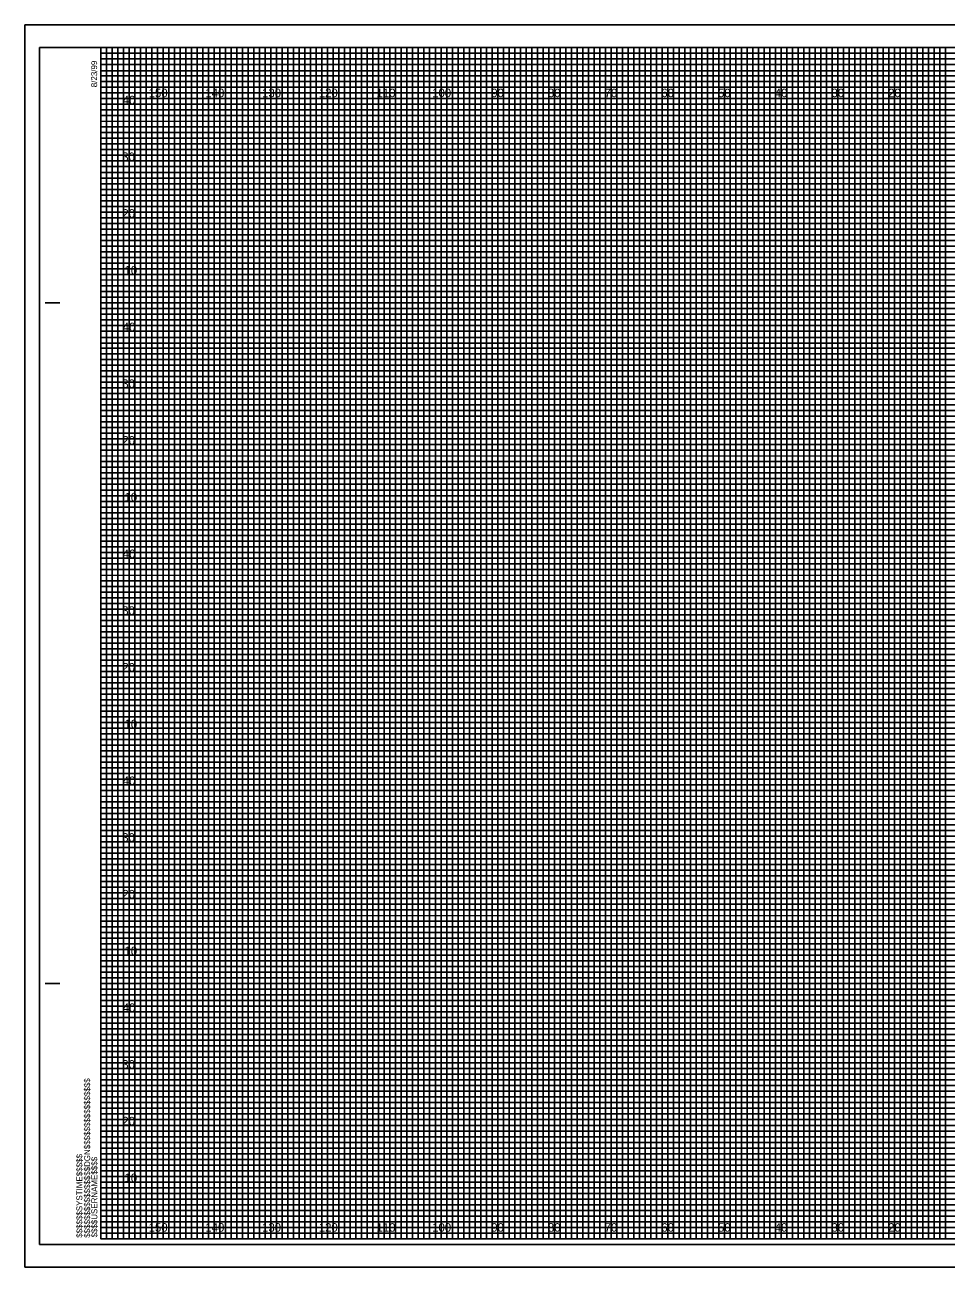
# Model space of a CAD drawing. Extents: x -13 to 323, y 215 to 434.
# Drawn here: x -13.4 to 149.1, y 215 to 434 of the extents above; entities that cross this region are included whole.
import ezdxf

# ---------------------------------------------------------------- set-up
doc = ezdxf.new("R2010")
doc.units = 0
for name, color, linetype in [('Exist Cross Section Cell', 7, 'Continuous'), ('Exist XS Center Line Elevation Label', 7, 'Continuous'), ('Exist XS Ground Line', 7, 'Continuous'), ('Prop XS Alignment Label', 7, 'Continuous'), ('Prop XS Ditch Standard Text', 7, 'Continuous'), ('Prop XS Earthwork Shape', 7, 'Continuous'), ('Prop XS Finish Grade', 7, 'Continuous'), ('Prop XS Finish Grade Earthwork', 7, 'Continuous'), ('Prop XS SE Text', 7, 'Continuous'), ('Prop XS Station Labels', 7, 'Continuous'), ('Prop XS Undercut Exc', 7, 'Continuous')]:
    doc.layers.add(name, color=color, linetype=linetype)

msp = doc.modelspace()

# ---------------------------------------------------------------- linework, layer by layer
at = {"layer": 'Exist XS Center Line Elevation Label'}
for points in [[(0, 430), (5, 430), (5, 220), (15, 220), (15, 430), (25, 430), (25, 220), (35, 220), (35, 430), (45, 430), (45, 220), (55, 220), (55, 430), (65, 430), (65, 220), (75, 220), (75, 430), (85, 430), (85, 220), (95, 220), (95, 430), (105, 430), (105, 220), (115, 220), (115, 430), (125, 430), (125, 220), (135, 220), (135, 430), (145, 430), (145, 220), (155, 220)], [(0, 425), (275, 425)], [(0, 405), (320, 405), (320, 415), (0, 415)], [(0, 385), (320, 385), (320, 395), (0, 395)], [(0, 365), (320, 365), (320, 375), (0, 375)], [(0, 345), (320, 345), (320, 355), (0, 355)], [(0, 325), (320, 325), (320, 335), (0, 335)], [(0, 305), (320, 305), (320, 315), (0, 315)], [(0, 285), (320, 285), (320, 295), (0, 295)], [(0, 265), (320, 265), (320, 275), (0, 275)], [(0, 245), (320, 245), (320, 255), (0, 255)], [(0, 225), (320, 225), (320, 235), (0, 235)]]:
    msp.add_lwpolyline(points, dxfattribs=at)
at = {"layer": 'Exist XS Ground Line'}
for p, q in [((10, 430), (0, 430)), ((10, 220), (10, 430)), ((30, 430), (20, 430)), ((20, 430), (20, 220)), ((30, 220), (30, 430)), ((50, 430), (40, 430)), ((40, 430), (40, 220)), ((50, 220), (50, 430)), ((70, 430), (60, 430)), ((60, 430), (60, 220)), ((70, 220), (70, 430)), ((90, 430), (80, 430)), ((80, 430), (80, 220)), ((90, 220), (90, 430)), ((110, 430), (100, 430)), ((100, 430), (100, 220)), ((110, 220), (110, 430)), ((130, 430), (120, 430)), ((120, 430), (120, 220)), ((130, 220), (130, 430)), ((150, 430), (140, 430)), ((140, 430), (140, 220)), ((20, 220), (10, 220)), ((40, 220), (30, 220)), ((60, 220), (50, 220)), ((80, 220), (70, 220)), ((100, 220), (90, 220)), ((120, 220), (110, 220)), ((140, 220), (130, 220))]:
    msp.add_line(p, q, dxfattribs=at)
for points in [[(0, 420), (320, 420), (320, 410), (0, 410)], [(0, 400), (320, 400), (320, 390), (0, 390)], [(0, 380), (320, 380), (320, 370), (0, 370)], [(0, 360), (320, 360), (320, 350), (0, 350)], [(0, 340), (320, 340), (320, 330), (0, 330)], [(0, 320), (320, 320), (320, 310), (0, 310)], [(0, 300), (320, 300), (320, 290), (0, 290)], [(0, 280), (320, 280), (320, 270), (0, 270)], [(0, 260), (320, 260), (320, 250), (0, 250)], [(0, 240), (320, 240), (320, 230), (0, 230)]]:
    msp.add_lwpolyline(points, dxfattribs=at)
at = {"layer": 'Prop XS Alignment Label'}
for p, q in [((0, 429), (260, 429)), ((260, 427.98), (0, 427.98)), ((0, 427.98), (0, 427)), ((0, 427), (260, 427)), ((260, 425.89), (0, 425.89)), ((0, 425.89), (0, 424)), ((0, 424), (320, 424))]:
    msp.add_line(p, q, dxfattribs=at)
for points in [[(0, 423), (270, 423), (320, 423), (320, 422), (0, 422)], [(0, 421), (320, 421), (320, 419), (0, 419)], [(0, 418), (320, 418), (320, 417), (0, 416.98)], [(0, 416), (320, 416), (320, 414), (0, 414)], [(0, 413), (320, 413), (320, 412), (0, 412)], [(0, 411), (320, 411), (320, 409), (0, 409)], [(0, 408), (320, 408), (320, 407), (0, 407)], [(0, 406), (320, 406), (320, 404), (0, 404)], [(0, 403), (320, 403), (320, 402), (0, 402)], [(0, 401), (320, 401), (320, 399), (0, 399)], [(0, 398), (320, 398), (320, 397), (0, 397)], [(0, 396), (320, 396), (320, 393.95), (320, 393), (320, 392), (0, 392)], [(0, 394), (320, 394), (320, 393), (0, 393)], [(0, 391), (320, 391), (320, 389), (0, 389.03)], [(0, 389.03), (320, 389), (320, 388), (0, 388)], [(0, 387), (320, 387), (320, 386), (0, 386)], [(0, 384), (320, 384), (320, 383), (0, 383)], [(0, 382), (320, 382), (320, 381), (0, 381)], [(-0.07, 378.89), (320, 378.89), (320, 377.88), (-0.07, 377.88)], [(0, 377), (320, 377), (320, 376), (0, 376)], [(0, 374), (320, 374), (320, 373), (0, 373)], [(0, 372), (320, 372), (320, 371), (0, 371)], [(0, 369), (320, 369), (320, 368), (0, 368)], [(0, 367), (320, 367), (320, 366), (0, 366)], [(0, 364), (320, 364), (320, 363), (0, 363)], [(0, 362), (320, 362), (320, 361), (0, 361)], [(0, 359), (320, 359), (319.99, 357.98), (0, 358)], [(0, 357), (320, 357), (320, 356), (0, 356)], [(0, 354), (320, 354), (320, 353), (0, 353)], [(0, 352), (320, 352), (320, 351), (0, 351)], [(0, 349), (320, 349), (320, 348), (0, 348)], [(0, 347), (320, 347), (320, 346), (0, 346)], [(0, 344), (320, 344), (320, 343), (0, 343)], [(0, 342), (320, 342), (320, 341), (0, 341)], [(0, 339), (320, 339), (320, 338), (0, 338)], [(0, 336.99), (320.07, 336.91), (320, 336), (0, 336)], [(0, 334), (320, 334), (320, 333), (0, 333)], [(0, 332), (320, 332), (320, 331), (0, 331)], [(0, 329), (320, 329), (320, 328), (0, 328)], [(0, 327), (320, 327), (320, 326), (0, 326)], [(0, 324), (320, 324), (320, 323), (0, 323)], [(0, 322), (320, 322), (320, 321), (0, 321)], [(0, 319), (320, 319), (320, 318), (0, 318)], [(0, 317), (320, 317), (320, 316), (0, 316)], [(0, 314), (320, 314), (320, 313), (0, 313)], [(0, 312), (320, 312), (320, 311), (0, 311)], [(0, 309), (320, 309), (320, 308), (0, 308)], [(0, 307), (320, 307), (320, 306), (0, 306)], [(0, 304), (320, 304), (320, 303), (0, 303)], [(0, 302), (320, 302), (320, 301), (0, 301)], [(0, 299), (320, 299), (319.99, 297.98), (0, 298)], [(0, 297), (320, 297), (320, 296), (0, 296)], [(0, 294), (320, 294), (320, 293), (0, 293)], [(0, 292), (320, 292), (320, 291), (0, 291)], [(0, 289), (320, 289), (320, 288), (0, 288)], [(0, 287), (320, 287), (320, 286), (0, 286)], [(0, 284), (320, 284), (320, 283), (0, 283)], [(0, 282), (320, 282), (320, 281), (0, 281)], [(0, 279), (320, 279), (320, 278), (0, 278)], [(0, 276.99), (320.07, 276.91), (320, 276), (0, 276)], [(0, 274), (320, 274), (320, 273), (0, 273)], [(0, 272), (320, 272), (320, 271), (0, 271)], [(0, 269), (320, 269), (320, 268), (0, 268)], [(0, 267), (320, 267), (320, 266), (0, 266)], [(0, 264), (320, 264), (320, 263), (0, 263)], [(0, 262), (320, 262), (320, 261), (0, 261)], [(0, 259), (320, 259), (320, 258), (0, 258)], [(0, 257), (320, 257), (320, 256), (0, 256)], [(0, 254), (320, 254), (320, 253), (0, 253)], [(0, 252), (320, 252), (320, 251), (0, 251)], [(0, 249), (320, 249), (320, 248), (0, 248)], [(0, 247), (320, 247), (320, 246), (0, 246)], [(0, 244), (320, 244), (320, 243), (0, 243)], [(0, 242), (320, 242), (320, 241), (0, 241)], [(0, 239), (320, 239), (320, 238), (0, 238)], [(0, 237), (320, 237), (320, 236), (0, 236)], [(0, 234), (320, 234), (320, 233), (0, 233)], [(0, 232), (320, 232), (320, 231), (0, 231)], [(0, 229), (320, 229), (320, 228), (0, 228)], [(0, 227), (320, 227), (320, 226), (0, 226)], [(0, 224), (320, 224), (320, 223), (0, 223)], [(0, 222), (320, 222), (320, 221), (0, 221)]]:
    msp.add_lwpolyline(points, dxfattribs=at)
at = {"layer": 'Prop XS Ditch Standard Text'}
for p, q in [((10, 220), (10, 430)), ((20, 220), (20, 430)), ((30, 220), (30, 430)), ((40, 220), (40, 430)), ((50, 220), (50, 430)), ((60, 220), (60, 430)), ((70, 220), (70, 430)), ((80, 220), (80, 430)), ((90, 220), (90, 430)), ((100, 220), (100, 430)), ((110, 220), (110, 430)), ((120, 220), (120, 430)), ((130, 220), (130, 430)), ((140, 220), (140, 430)), ((0, 420), (320, 420)), ((0, 410), (320, 410)), ((0, 400), (320, 400)), ((0, 390), (320, 390)), ((0, 380), (320, 380)), ((0, 370), (320, 370)), ((0, 360), (320, 360)), ((0, 350), (320, 350)), ((0, 340), (320, 340)), ((0, 330), (320, 330)), ((0, 320), (320, 320)), ((0, 310), (320, 310)), ((0, 300), (320, 300)), ((0, 290), (320, 290)), ((0, 280), (320, 280)), ((0, 270), (320, 270)), ((0, 260), (320, 260)), ((0, 250), (320, 250)), ((0, 240), (320, 240)), ((0, 230), (320, 230))]:
    msp.add_line(p, q, dxfattribs=at)
at = {"layer": 'Prop XS Earthwork Shape'}
for points in [[(0, 220), (1, 220), (1, 430), (2, 430), (2, 220)], [(2, 220), (3, 220), (3, 430), (4, 430), (4, 220)], [(5, 220), (6, 220), (6, 430), (7, 430), (7, 220)], [(7, 220), (8, 220), (8, 430), (9, 430), (9, 220)], [(10, 220), (11, 220), (11, 430), (12, 430), (12, 220)], [(12, 220), (13, 220), (13, 430), (14, 430), (14, 220)], [(15, 220), (16, 220), (16, 430), (17, 430), (17, 220)], [(17, 220), (18, 220), (18, 430), (19, 430), (19, 220)], [(20, 220), (21, 220), (21, 430), (22, 430), (22, 220)], [(22, 220), (23, 220), (23, 430), (24, 430), (24, 220)], [(25, 220), (26, 220), (26, 430), (27, 430), (27, 220)], [(27, 220), (28, 220), (28, 430), (29, 430), (29, 220)], [(30, 220), (31, 220), (31, 430), (32, 430), (32, 220)], [(32, 220), (33, 220), (33, 430), (34, 430), (34, 220)], [(35, 220), (36, 220), (36, 430), (37, 430), (37, 220)], [(37, 220), (38, 220), (38, 430), (39, 430), (39, 220)], [(40, 220), (41, 220), (41, 430), (42, 430), (42, 220)], [(42, 220), (43, 220), (43, 430), (44, 430), (44, 220)], [(45, 220), (46, 220), (46, 430), (47, 430), (47, 220)], [(47, 220), (48, 220), (48, 430), (49, 430), (49, 220)], [(50, 220), (51, 220), (51, 430), (52, 430), (52, 220)], [(52, 220), (53, 220), (53, 430), (54, 430), (54, 220)], [(55, 220), (56, 220), (56, 430), (57, 430), (57, 220)], [(57, 220), (58, 220), (58, 430), (59, 430), (59, 220)], [(60, 220), (61, 220), (61, 430), (62, 430), (62, 220)], [(62, 220), (63, 220), (63, 430), (64, 430), (64, 220)], [(65, 220), (66, 220), (66, 430), (67, 430), (67, 220)], [(67, 220), (68, 220), (68, 430), (69, 430), (69, 220)], [(70, 220), (71, 220), (71, 430), (72, 430), (72, 220)], [(72, 220), (73, 220), (73, 430), (74, 430), (74, 220)], [(75, 220), (76, 220), (76, 430), (77, 430), (77, 220)], [(77, 220), (78, 220), (78, 430), (79, 430), (79, 220)], [(80, 220), (81, 220), (81, 430), (82, 430), (82, 220)], [(82, 220), (83, 220), (83, 430), (84, 430), (84, 220)], [(85, 220), (86, 220), (86, 430), (87, 430), (87, 220)], [(87, 220), (88, 220), (88, 430), (89, 430), (89, 220)], [(90, 220), (91, 220), (91, 430), (92, 430), (92, 220)], [(92, 220), (93, 220), (93, 430), (94, 430), (94, 220)], [(95, 220), (96, 220), (96, 430), (97, 430), (97, 220)], [(97, 220), (98, 220), (98, 430), (99, 430), (99, 220)], [(100, 220), (101, 220), (101, 430), (102, 430), (102, 220)], [(102, 220), (103, 220), (103, 430), (104, 430), (104, 220)], [(105, 220), (106, 220), (106, 430), (107, 430), (107, 220)], [(107, 220), (108, 220), (108, 430), (109, 430), (109, 220)], [(110, 220), (111, 220), (111, 430), (112, 430), (112, 220)], [(112, 220), (113, 220), (113, 430), (114, 430), (114, 220)], [(115, 220), (116, 220), (116, 430), (117, 430), (117, 220)], [(117, 220), (118, 220), (118, 430), (119, 430), (119, 220)], [(120, 220), (121, 220), (121, 430), (122, 430), (122, 220)], [(122, 220), (123, 220), (123, 430), (124, 430), (124, 220)], [(125, 220), (126, 220), (126, 430), (127, 430), (127, 220)], [(127, 220), (128, 220), (128, 430), (129, 430), (129, 220)], [(130, 220), (131, 220), (131, 430), (132, 430), (132, 220)], [(132, 220), (133, 220), (133, 430), (134, 430), (134, 220)], [(135, 220), (136, 220), (136, 430), (137, 430), (137, 220)], [(137, 220), (138, 220), (138, 430), (139, 430), (139, 220)], [(140, 220), (141, 220), (141, 430), (142, 430), (142, 220)], [(142, 220), (143, 220), (143, 430), (144, 430), (144, 220)], [(145, 220), (146, 220), (146, 430), (147, 430), (147, 220)], [(147, 220), (148, 220), (148, 430), (149, 430), (149, 220)]]:
    msp.add_lwpolyline(points, dxfattribs=at)
at = {"layer": 'Prop XS Finish Grade Earthwork'}
for p, q in [((323.3, 434), (-13.4, 434)), ((-13.4, 434), (-13.4, 215)), ((-13.4, 215), (323.3, 215))]:
    msp.add_line(p, q, dxfattribs=at)
at = {"layer": 'Prop XS SE Text'}
for p, q in [((-9.8, 385), (-7.3, 385)), ((-9.7, 385), (-7.2, 385)), ((-9.8, 265), (-7.3, 265)), ((-9.7, 265), (-7.2, 265)), ((0, 220), (0, 220)), ((0, 220), (0, 220)), ((0, 220), (0, 220)), ((0, 220), (0, 220)), ((0, 220), (0, 220)), ((0, 220), (0, 220)), ((0, 220), (0, 220))]:
    msp.add_line(p, q, dxfattribs=at)
msp.add_lwpolyline([(320, 430), (0, 430), (0, 220), (320, 220)], close=True, dxfattribs=at)
at = {"layer": 'Prop XS Station Labels'}
msp.add_lwpolyline([(-10.8, 219), (322.4, 219), (322.4, 430), (-10.8, 430)], close=True, dxfattribs=at)
at = {"layer": 'Prop XS Undercut Exc'}
msp.add_lwpolyline([(-13.4, 215), (323.3, 215), (323.3, 434), (-13.4, 434)], close=True, dxfattribs=at)

# ---------------------------------------------------------------- texts
at = {"layer": 'Exist Cross Section Cell'}
for s, p in [('150', (8.44, 421.25)), ('140', (18.44, 421.25)), ('130', (28.44, 421.25)), ('120', (38.44, 421.25)), ('110', (48.62, 421.25)), ('100', (58.44, 421.25)), ('90', (68.86, 421.25)), ('80', (78.86, 421.25)), ('70', (88.86, 421.25)), ('60', (98.86, 421.25)), ('50', (108.86, 421.25)), ('40', (118.86, 421.25)), ('30', (128.86, 421.25)), ('20', (138.86, 421.25)), ('150', (8.44, 221.25)), ('140', (18.44, 221.25)), ('130', (28.44, 221.25)), ('120', (38.44, 221.25)), ('110', (48.62, 221.25)), ('100', (58.44, 221.25)), ('90', (68.86, 221.25)), ('80', (78.86, 221.25)), ('70', (88.86, 221.25)), ('60', (98.86, 221.25)), ('50', (108.86, 221.25)), ('40', (118.86, 221.25)), ('30', (128.86, 221.25)), ('20', (138.86, 221.25))]:
    msp.add_text(s, height=1.5, dxfattribs=at).set_placement(p)
at = {"layer": 'Prop XS Finish Grade'}
for s, p in [('40', (3.87, 420)), ('30', (3.78, 410)), ('20', (3.8, 400)), ('10', (4.17, 390)), ('40', (3.87, 380)), ('30', (3.78, 370)), ('20', (3.8, 360)), ('10', (4.17, 350)), ('40', (3.87, 340)), ('30', (3.78, 330)), ('20', (3.8, 320)), ('10', (4.17, 310)), ('40', (3.87, 300)), ('30', (3.78, 290)), ('20', (3.8, 280)), ('10', (4.17, 270)), ('40', (3.87, 260)), ('30', (3.78, 250)), ('20', (3.8, 240)), ('10', (4.17, 230))]:
    msp.add_text(s, height=1.5, dxfattribs=at).set_placement(p)
at = {"layer": 'Prop XS SE Text'}
for s, p in [('8/23/99', (-0.65, 423)), ('$$$$$$$$$$$$$$$$DGN$$$$$$$$$$$$$$$$', (-1.88, 220.18)), ('$$$$$$SYSTIME$$$$$', (-3.26, 220.18)), ('$$$$USERNAME$$$$', (-0.62, 220.23))]:
    msp.add_text(s, height=1.05, rotation=90, dxfattribs=at).set_placement(p)

doc.saveas('drawing.dxf')
